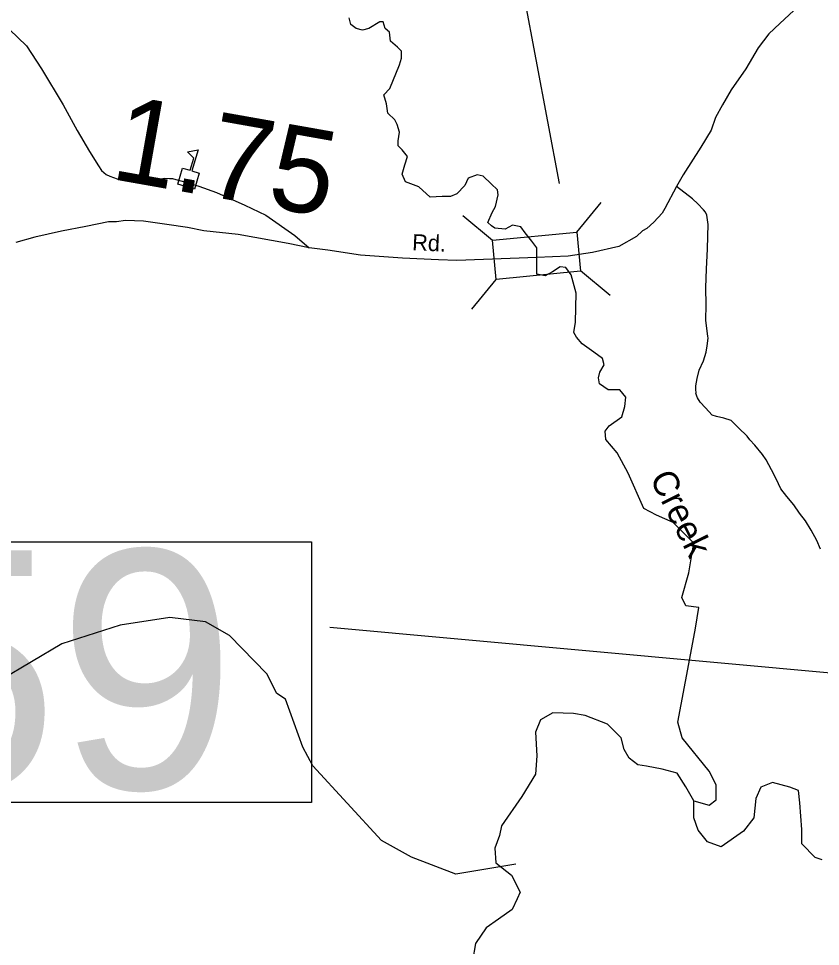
# Model space of a CAD drawing. Extents: x 2093524 to 2270757, y 289120 to 570408.
# Drawn here: x 2215806 to 2220506, y 398711 to 404154 of the extents above; entities that cross this region are included whole.
import ezdxf

# ---------------------------------------------------------------- set-up
doc = ezdxf.new("R2010")
doc.units = 0
for name, color, linetype in [('Exist Cultural Educational Facility High CELL', 7, 'Continuous'), ('Exist Hydrographic Creek Single Shore', 7, 'Continuous'), ('Exist Hydrographic Creek Single Shore Label', 7, 'Continuous'), ('Exist Hydrographic Misc Water Feature', 7, 'Continuous'), ('Exist Road Non-System Type 51', 7, 'Continuous'), ('Exist Road Primary US Structure Standard Bridge Number Label', 7, 'Continuous'), ('Exist Road Secondary Mileage Hundredths English Label', 7, 'Continuous'), ('Exist Road Secondary Structure Standard Bridge CELL', 7, 'Continuous'), ('Exist Road Secondary Structure Standard Bridge Number Label', 7, 'Continuous'), ('Exist Road Secondary Type 51 Attributed', 7, 'Continuous'), ('Exist Road Secondary Type 51 Label', 7, 'Continuous')]:
    doc.layers.add(name, color=color, linetype=linetype)

msp = doc.modelspace()

# ---------------------------------------------------------------- linework, layer by layer
at = {"layer": 'Exist Cultural Educational Facility High CELL'}
msp.add_lwpolyline([(2216738.7, 403183.6), (2216767.1, 403277.3), (2216811.2, 403263.9), (2216833, 403335.8), (2216795, 403372.6), (2216857.6, 403384.1), (2216820.4, 403261.1), (2216864.4, 403247.8), (2216836, 403154.1)], close=True, dxfattribs=at)
at = {"layer": 'Exist Hydrographic Creek Single Shore'}
for points in [[(2218842.9, 402753), (2218844.1, 402809.5), (2218813.7, 402848.9), (2218776, 402897.3), (2218750.9, 402933.2), (2218700.7, 402942.1), (2218657.7, 402918.8), (2218598.5, 402924.2), (2218578.8, 402938.5), (2218557.3, 402958.3), (2218582.4, 403015.6), (2218602.1, 403051.5), (2218616.5, 403119.6), (2218612.9, 403150.1), (2218577, 403184.1), (2218528.6, 403229), (2218494.5, 403237.9), (2218440.8, 403218.2), (2218421, 403175.2), (2218374.4, 403126.8), (2218336.8, 403110.6), (2218288.4, 403110.6), (2218218.5, 403107.1), (2218152.1, 403166.2), (2218073.3, 403196.7), (2218053.5, 403241.5), (2218069.7, 403295.3), (2218085.8, 403345.5), (2218055.3, 403384.9), (2218030.2, 403408.2), (2218030.2, 403436.9), (2218039.2, 403487.1), (2218024.8, 403531.9), (2218010.5, 403560.6), (2217971.1, 403600.1), (2217962.1, 403653.8), (2217946, 403705.8), (2217981.8, 403743.5), (2218039.2, 403883.3), (2218049.9, 403922.8), (2218049.9, 403962.2), (2218026.6, 403987.3), (2217985.4, 404021.4), (2217980, 404075.1), (2217954.9, 404094.9), (2217942.4, 404134.3), (2217922.7, 404134.3), (2217858.1, 404094.9), (2217822.3, 404085.9), (2217784.7, 404094.9), (2217754.1, 404120), (2217743.4, 404159.4)], [(2219763.8, 399564.5), (2219854.7, 399539), (2219894.7, 399571.7), (2219894.7, 399659), (2219854.7, 399739), (2219695.8, 399934), (2219669.7, 400026.4), (2219734.8, 400367.9), (2219774.7, 400578.8), (2219792.9, 400698.8), (2219716.6, 400709.7), (2219694.8, 400757), (2219734.8, 400902.4), (2219752.9, 401007.8), (2219763.8, 401076.9), (2219643.9, 401196.9), (2219545.7, 401240.5), (2219471.2, 401279.3), (2219380.2, 401486.7), (2219315.6, 401606.5), (2219247.5, 401685.4), (2219243.9, 401733.8), (2219267.2, 401764.3), (2219342.5, 401818.1), (2219360.4, 401879), (2219365.8, 401932.8), (2219330, 401975.8), (2219261.8, 401975.8), (2219211.6, 402011.7), (2219204.5, 402045.8), (2219213.4, 402079.8), (2219238.5, 402122.9), (2219227.8, 402160.5), (2219177.6, 402196.4), (2219109.5, 402246.6), (2219075.4, 402286), (2219061, 402312.9), (2219070, 402373.8), (2219073.6, 402542.4), (2219044.9, 402649.9), (2219014.4, 402692.9), (2218980.4, 402698.3), (2218935.6, 402667.8), (2218892.5, 402644.5), (2218844.1, 402655.3), (2218842.9, 402753)], [(2219763.8, 399564.5), (2219716.6, 399648.1), (2219665.7, 399728.1), (2219578.4, 399749.9), (2219487.5, 399768.1), (2219436.6, 399775.3), (2219385.7, 399815.3), (2219356.6, 399866.2), (2219338.5, 399935.3), (2219305.7, 399968), (2219258.5, 400015.3), (2219127.6, 400066.2), (2219058.5, 400077.1), (2218938.5, 400080.7), (2218865.8, 400040.7), (2218836.7, 399968), (2218844, 399829.9), (2218836.7, 399720.8), (2218756.8, 399589.9), (2218636.8, 399419), (2218625.9, 399360.9), (2218596.8, 399288.1), (2218604.1, 399200.9), (2218695, 399128.2), (2218745.9, 399030), (2218727.7, 398990), (2218698.6, 398928.2), (2218618.6, 398870), (2218545.9, 398819.1), (2218484.1, 398728.2), (2218465.9, 398626.4)], [(2220516.4, 399219.1), (2220476.4, 399233.6), (2220396.5, 399313.6), (2220396.5, 399397.2), (2220385.5, 399553.5), (2220378.3, 399626.3), (2220327.4, 399644.4), (2220225.6, 399673.5), (2220156.5, 399644.4), (2220127.4, 399579), (2220116.5, 399466.3), (2220054.7, 399386.3), (2219923.8, 399295.4), (2219843.8, 399324.5), (2219789.3, 399393.6), (2219763.8, 399466.3), (2219763.8, 399564.5)]]:
    msp.add_lwpolyline(points, dxfattribs=at)
at = {"layer": 'Exist Hydrographic Misc Water Feature'}
msp.add_lwpolyline([(2218721, 399194.4), (2218368.7, 399133.9), (2218109.7, 399234.1), (2217933.8, 399332.8), (2217530.8, 399770.4), (2217471.8, 399879.8), (2217369.7, 400160.6), (2217319.8, 400194.5), (2217260.8, 400310.4), (2217042.8, 400534.5), (2216900.7, 400616.1), (2216691.8, 400639.9), (2216400.8, 400596.5), (2216059.8, 400485.2), (2215703.6, 400275.8), (2215594.7, 400281.3), (2215452.6, 400398.9), (2215317.7, 400670.5), (2215308.7, 400762.5), (2215206.8, 400971.2), (2214963.8, 401320.5), (2214911.7, 401528.1), (2214833.8, 402008.6), (2214836.7, 402743.2)], dxfattribs=at)
at = {"layer": 'Exist Road Non-System Type 51'}
for points in [[(2215704.3, 404137.3), (2215851.3, 403994.3), (2215940.1, 403859.1), (2216067.5, 403647.9), (2216148.5, 403498.4), (2216221.4, 403374.9), (2216273.9, 403289.6), (2216292, 403263.6), (2216318.1, 403239.8), (2216340.2, 403229.9), (2216382.6, 403214.3), (2216428.3, 403206.5), (2216538.4, 403201.3), (2216616.3, 403208), (2216658.2, 403218), (2216690.3, 403216.4), (2216708.3, 403216.3), (2216728.2, 403210.7), (2216772.3, 403199), (2216862.6, 403171.6), (2216966.8, 403134.4), (2217131.3, 403059.3), (2217255.4, 403000.4), (2217424.2, 402881.6), (2217508.8, 402810.1)], [(2220507.6, 401041.5), (2220485.3, 401093.2), (2220452.7, 401153.2), (2220418.4, 401206.7), (2220384.2, 401252.6), (2220349.7, 401302.2), (2220309.4, 401349.9), (2220275.2, 401395.8), (2220246.8, 401453.4), (2220220.3, 401507.4), (2220188, 401565.2), (2220166, 401596.7), (2220121.5, 401652.4), (2220093.3, 401682.5), (2220077.3, 401704.1), (2220026.8, 401754), (2219982.7, 401795.6), (2219940.7, 401809.2), (2219896.6, 401818.9), (2219872.5, 401826.9), (2219832.3, 401870.4), (2219801.8, 401904.1), (2219785.6, 401930), (2219775.6, 401954.2), (2219777.6, 401958.1), (2219777.4, 401964), (2219775.6, 401972.2), (2219775.2, 402000.1), (2219782.9, 402041.9), (2219794.7, 402092.2), (2219820.4, 402146.1), (2219835.8, 402196.3), (2219841.5, 402234.3), (2219847.3, 402278.4), (2219847.2, 402290.2), (2219840.9, 402336.3), (2219834.7, 402384.3), (2219836.1, 402474.1), (2219835.5, 402574.2), (2219838.7, 402686.3), (2219843.6, 402802.3), (2219847.1, 402878), (2219848.8, 402946.2), (2219840.4, 403000.2), (2219832.2, 403018), (2219820.3, 403032.1), (2219787.9, 403067.8), (2219755.7, 403097.3), (2219663.3, 403168.7)]]:
    msp.add_lwpolyline(points, dxfattribs=at)
at = {"layer": 'Exist Road Primary US Structure Standard Bridge Number Label'}
msp.add_line((2221759.8, 400204.3), (2217629.7, 400582.4), dxfattribs=at)
msp.add_lwpolyline([(2214945.3, 401085.3), (2217521.9, 401085.3), (2217521.9, 399556), (2214945.3, 399556)], close=True, dxfattribs=at)
at = {"layer": 'Exist Road Secondary Structure Standard Bridge CELL'}
for p, q in [((2219077.6, 402900.8), (2219221.5, 403075.5)), ((2218409.3, 402998.2), (2218584, 402854.2)), ((2219099.3, 402675.5), (2219274, 402531.6)), ((2218462.3, 402449), (2218606.3, 402623.7))]:
    msp.add_line(p, q, dxfattribs=at)
msp.add_lwpolyline([(2218584, 402854.2), (2219077.5, 402901.9), (2219099.7, 402671.4), (2218606.3, 402623.7)], close=True, dxfattribs=at)
at = {"layer": 'Exist Road Secondary Structure Standard Bridge Number Label'}
msp.add_line((2218976.8, 403185.9), (2218274, 406929.2), dxfattribs=at)
at = {"layer": 'Exist Road Secondary Type 51 Attributed'}
for points in [[(2220459, 404305.7), (2220268.5, 404124.5), (2220203, 404064.2), (2220141.6, 403981.8), (2220069, 403858.9), (2219983.8, 403736.5), (2219931.9, 403647.5), (2219891.1, 403573.4), (2219865.1, 403499.2), (2219805.8, 403399), (2219700.8, 403237.1), (2219663.3, 403168.7), (2219594.2, 403040.5), (2219578.5, 403012.3), (2219528.9, 402959.8), (2219489.2, 402923.5), (2219463.3, 402909.6), (2219427.8, 402876.1), (2219324, 402816.7), (2219170.6, 402780.9), (2219027, 402760.7), (2218842.9, 402753)], [(2218842.9, 402753), (2218374.8, 402734.1), (2218267, 402739.2), (2218056.9, 402748), (2217811, 402766.3), (2217618.7, 402794.8), (2217508.8, 402810.1), (2217386.6, 402835.1), (2217092.7, 402887.2), (2216892.5, 402909.5), (2216796.4, 402928.2), (2216674, 402945.4), (2216538, 402965.5), (2216432.1, 402968.6), (2216380.2, 402962.4), (2216332.3, 402962.1), (2216200.6, 402935.2), (2216056.6, 402906.2), (2215901.1, 402870.9), (2215789.3, 402840.4)]]:
    msp.add_lwpolyline(points, dxfattribs=at)

# ---------------------------------------------------------------- texts
at = {"layer": 'Exist Hydrographic Creek Single Shore Label'}
msp.add_text('Creek', height=150, rotation=296.3365, dxfattribs=at).set_placement((2219503.2, 401459.8))
at = {"layer": 'Exist Road Primary US Structure Standard Bridge Number Label'}
msp.add_text('59', height=1400, dxfattribs=at).set_placement((2214995.5, 399635.1))
at = {"layer": 'Exist Road Secondary Mileage Hundredths English Label'}
msp.add_text('1.75', height=500, rotation=349.9543, dxfattribs=at).set_placement((2216336.4, 403215.3))
at = {"layer": 'Exist Road Secondary Type 51 Label'}
msp.add_text('Rd.', height=95, rotation=357.6095, dxfattribs=at).set_placement((2218111.6, 402795))

doc.saveas('drawing.dxf')
